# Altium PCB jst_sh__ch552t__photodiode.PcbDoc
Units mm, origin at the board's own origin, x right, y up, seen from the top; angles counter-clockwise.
Board outline 56 x 30 mm, 2 copper layers (Top, Bottom), stack 0 mm thick; 18 components, 10 nets, 67 pads, 25 vias.
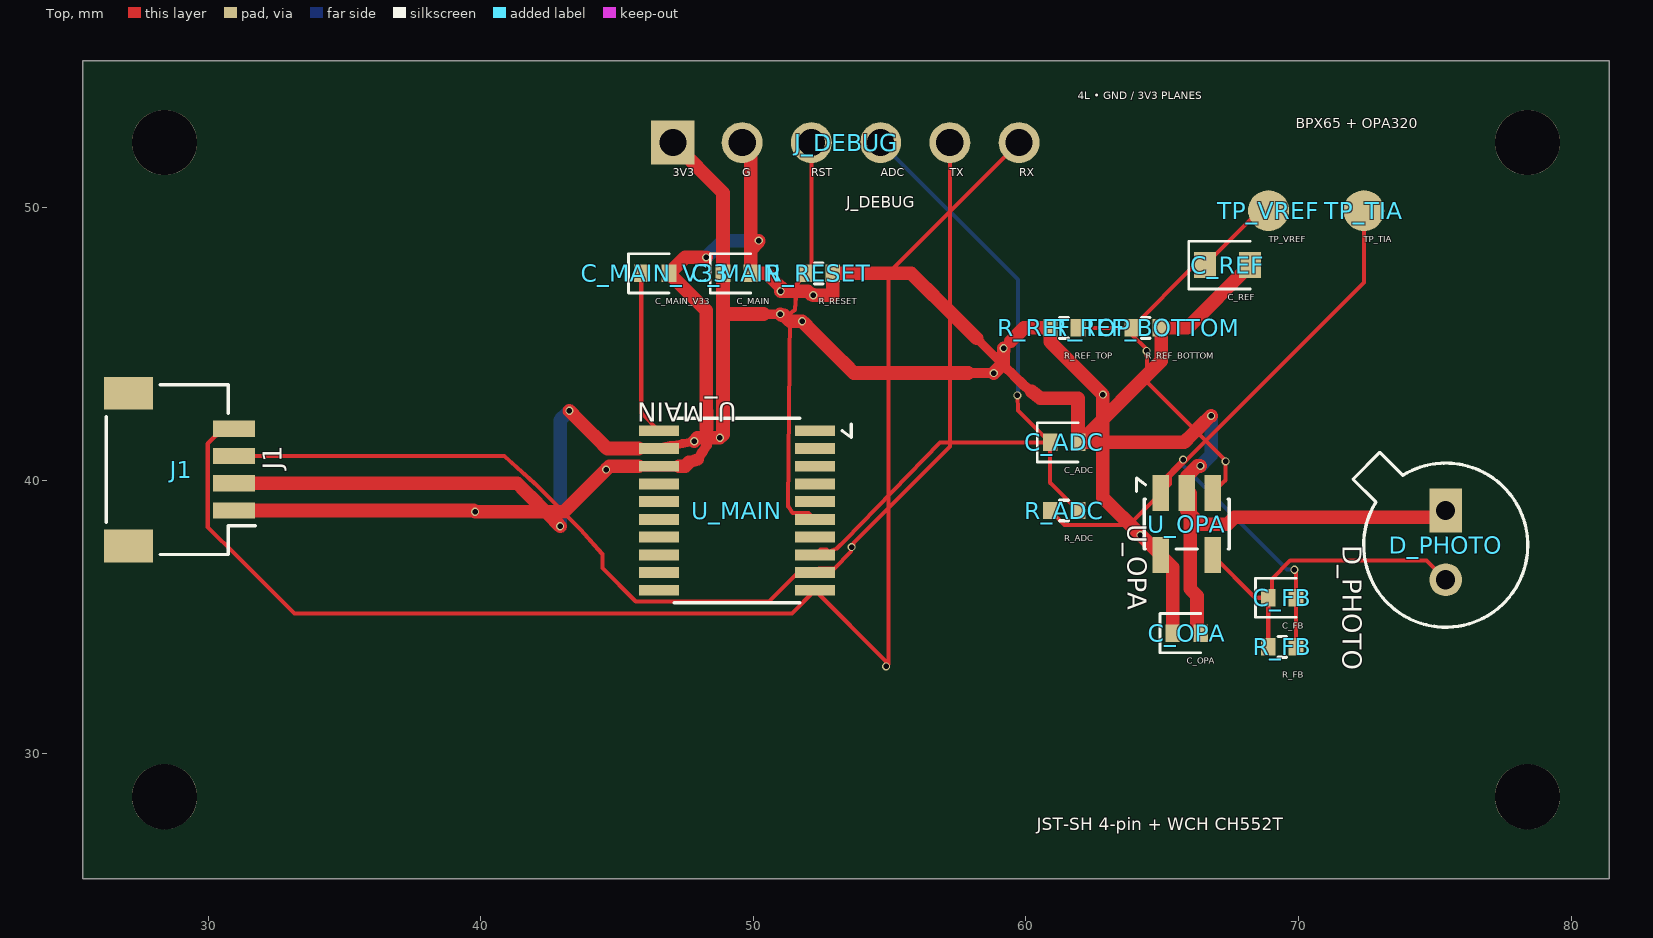
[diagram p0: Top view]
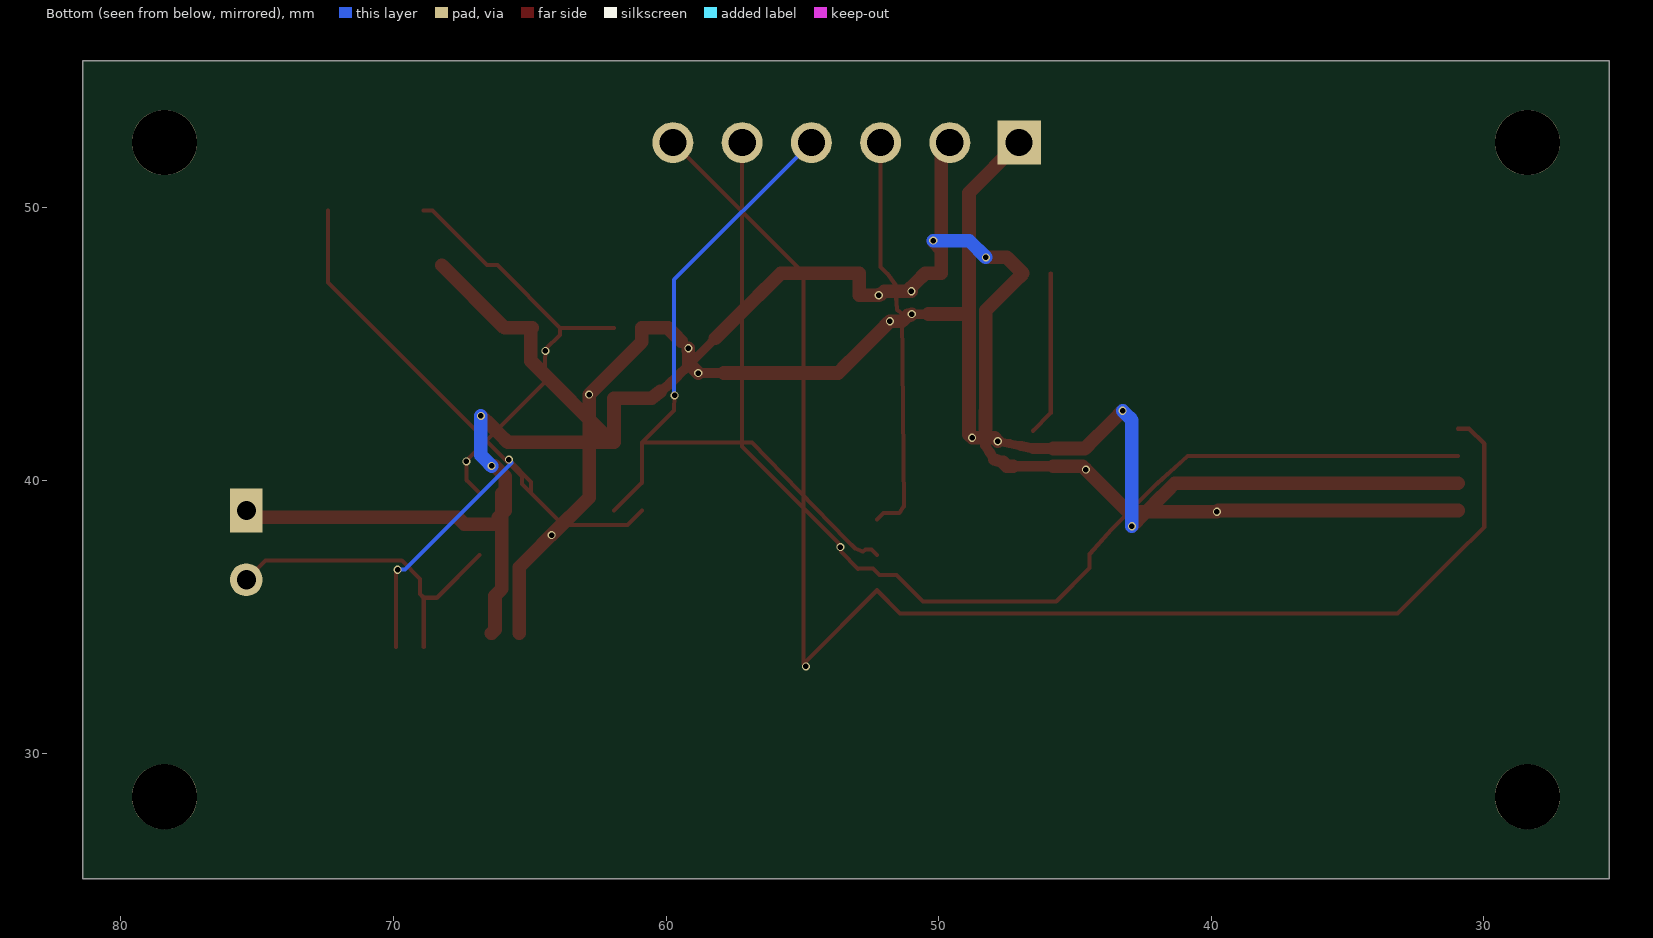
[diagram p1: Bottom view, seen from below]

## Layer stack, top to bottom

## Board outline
25.4,55.4 81.4,55.4 81.4,25.4 25.4,25.4

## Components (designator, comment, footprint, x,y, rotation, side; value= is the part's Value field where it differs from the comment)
C_ADC "" TSCIRCUIT-1.5600x0.6400mm 61.4,41.4 r0 top
C_FB "" TSCIRCUIT-1.5600x0.6400mm 69.4,35.7 r0 top
C_MAIN "" TSCIRCUIT-1.5600x0.6400mm 49.4,47.6 r0 top
C_MAIN_V33 "" TSCIRCUIT-1.5600x0.6400mm 46.4,47.6 r0 top
C_OPA "" TSCIRCUIT-1.5600x0.6400mm 65.9,34.4 r0 top
C_REF "" TSCIRCUIT-2.4500x0.9500mm 67.4,47.9 r0 top
D_PHOTO "" TSCIRCUIT-1.2000x3.9400mm 75.4,37.73 r270 top
J1 "" TSCIRCUIT-5.5500x6.8000mm 28.95,40.4 r90 top
J_DEBUG "" TSCIRCUIT-14.2000x1.5000mm 53.4,52.4 r0 top
R_ADC "" TSCIRCUIT-1.5600x0.6400mm 61.4,38.9 r0 top
R_FB "" TSCIRCUIT-1.5600x0.6400mm 69.4,33.9 r0 top
R_REF_BOTTOM "" TSCIRCUIT-1.5600x0.6400mm 64.4,45.6 r0 top
R_REF_TOP "" TSCIRCUIT-1.5600x0.6400mm 61.4,45.6 r0 top
R_RESET "" TSCIRCUIT-1.5600x0.6400mm 52.4,47.6 r0 top
TP_TIA "" TSCIRCUIT-1.5000x1.5000mm 72.4,49.9 r0 top
TP_VREF "" TSCIRCUIT-1.5000x1.5000mm 68.9,49.9 r0 top
U_MAIN "" TSCIRCUIT-7.2000x6.2500mm 49.4,38.9 r180 top
U_OPA "" TSCIRCUIT-2.5000x3.6000mm 65.9,38.4 r270 top

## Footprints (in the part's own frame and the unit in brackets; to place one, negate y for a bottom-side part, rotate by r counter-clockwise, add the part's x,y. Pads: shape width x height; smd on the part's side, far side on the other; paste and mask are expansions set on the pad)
TSCIRCUIT-1.2000x3.9400mm [mm]
  rect 1.6x1.2 hole 0.7: 1(-1.17,0)
  round 1.2 hole 0.7: 2(1.37,0)
  silkscreen extent -3.3,-3.4 3.11,3.01
TSCIRCUIT-1.5000x1.5000mm [mm]
  round 1.5 smd: 1(0,0)
TSCIRCUIT-1.5600x0.6400mm [mm]
  rect 0.54x0.64 smd: 1(-0.51,0) 2(0.51,0)
  silkscreen extent -0.98,-0.72 0.51,0.72
TSCIRCUIT-2.4500x0.9500mm [mm]
  rect 0.8x0.95 smd: 1(-0.825,0) 2(0.825,0)
  silkscreen extent -1.43,-0.87 0.82,0.87
TSCIRCUIT-2.5000x3.6000mm [mm]
  rect 1.325x0.6 smd: 1(-1.138,-0.95) 2(-1.138,0) 3(-1.138,0.95) 4(1.137,0.95) 5(1.137,-0.95)
  silkscreen extent -1.69,-1.84 0.91,1.56
TSCIRCUIT-5.5500x6.8000mm [mm]
  rect 1.2x1.8 smd: 1(-2.8,1.875) 1(2.8,1.875)
  rect 0.6x1.55 smd: 1(-1.5,-2) 2(-0.5,-2) 3(0.5,-2) 4(1.5,-2)
  silkscreen extent -3.11,-2.77 3.11,2.69
TSCIRCUIT-7.2000x6.2500mm [mm]
  rect 1.475x0.4 smd: 1(-2.862,-2.925) 2(-2.862,-2.275) 3(-2.862,-1.625) 4(-2.862,-0.975) 5(-2.862,-0.325) 6(-2.862,0.325) 7(-2.862,0.975) 8(-2.862,1.625) 9(-2.862,2.275) 10(-2.862,2.925) 11(2.863,2.925) 12(2.863,2.275) 13(2.863,1.625) 14(2.863,0.975) 15(2.863,0.325) 16(2.863,-0.325) 17(2.863,-0.975) 18(2.863,-1.625) 19(2.863,-2.275) 20(2.863,-2.925)
  silkscreen extent -4.19,-3.38 2.31,3.39
TSCIRCUIT-14.2000x1.5000mm [mm]
  rect 1.6x1.6 hole 1: 1(-6.35,0)
  round 1.5 hole 1: 2(-3.81,0) 3(-1.27,0) 4(1.27,0) 5(3.81,0) 6(6.35,0)

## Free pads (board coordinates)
  round 2.4 hole 2.4 unplated: NPTH-1(28.4,28.4) NPTH-2(78.4,52.4) NPTH-3(78.4,28.4) NPTH-4(28.4,52.4)

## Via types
v1: diameter 0.3, hole 0.2, Top to Bottom, 25 vias

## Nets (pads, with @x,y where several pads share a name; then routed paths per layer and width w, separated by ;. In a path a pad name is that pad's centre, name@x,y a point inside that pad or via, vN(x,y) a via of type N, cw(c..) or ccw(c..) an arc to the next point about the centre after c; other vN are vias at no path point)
ADC_IN: C_ADC.1 J_DEBUG.4 R_ADC.2 U_MAIN.8 | length 26.9
  Top w0.15: U_MAIN.8 52.463,37.476 52.678,37.476 52.791,37.392 53.072,37.516 53.357,37.795 56.841,41.4 C_ADC.1 ; v1(59.686,43.125) 59.715,42.575 C_ADC.1 ; R_ADC.2 60.89,39.92 C_ADC.1
  Bottom w0.15: J_DEBUG.4 59.703,47.367 59.703,43.235 59.703,43.166 v1(59.686,43.125)
GND: C_ADC.2 C_MAIN.2 C_MAIN_V33.2 C_OPA.2 C_REF.2 D_PHOTO.1 J1.1@30.95,38.9 J_DEBUG.2 R_REF_BOTTOM.2 R_RESET.2 U_MAIN.18 U_OPA.2 | length 86.7
  Top w0.325: 48.282,41.896 48.283,41.414 48.29,41.294 ; 58.193,45.213 58.536,44.872 58.878,44.531 59.221,44.191
  Top w0.35: 59.221,44.191 59.564,43.85
  Top w0.375: 47.962,40.775 48.126,41.034 48.29,41.294 ; 59.564,43.85 59.906,43.509 60.216,43.267
  Top w0.4: U_MAIN.18@45.8,40.525 U_MAIN.18 U_MAIN.18@47.275,40.525
  Top w0.45: 47.643,40.671 47.962,40.775
  Top w0.5: J1.1@30.95,38.9 39.749,38.9 v1(39.794,38.855) 40.26,38.855 40.726,38.855 41.192,38.855 41.657,38.855 42.123,38.855 42.589,38.855 43.055,38.855 43.363,39.163 43.671,39.471 43.979,39.779 44.287,40.087 44.595,40.395 v1(44.6,40.4) 44.725,40.525 U_MAIN.18@45.8,40.525 ; 47.275,40.525 47.496,40.525 47.643,40.671 ; v1(48.268,48.187) 47.497,48.187 C_MAIN_V33.2 47.25,47.26 47.591,46.919 47.931,46.579 48.271,46.239 48.273,45.756 48.274,45.274 48.275,44.791 48.276,44.309 48.277,43.826 48.278,43.344 48.28,42.861 48.281,42.379 48.282,41.896 ; J_DEBUG.2 49.91,52.08 C_MAIN.2 ; v1(50.2,48.8) 50.172,48.772 50.172,48.741 49.91,48.48 C_MAIN.2 ; 58.193,45.213 57.85,45.554 57.508,45.895 57.165,46.236 56.823,46.577 56.48,46.918 56.137,47.259 55.795,47.6 55.314,47.6 54.833,47.6 54.352,47.6 53.872,47.6 53.391,47.6 R_RESET.2 52.91,46.8 v1(52.2,46.8) 52.165,46.835 52.108,46.835 52,46.942 51.501,46.942 v1(51.001,46.942) 51.143,46.952 51.143,46.956 50.821,47.278 50.499,47.6 50.204,47.6 C_MAIN.2 ; 60.216,43.267 60.525,43.025 61.91,43.025 C_ADC.2 ; v1(66.402,40.535) 66.285,40.535 65.9,40.15 65.9,40.033 U_OPA.2 ; C_OPA.2 66.4,34.4 66.275,34.525 66.275,35.775 66.025,36.025 66.025,39.525 65.912,39.525 U_OPA.2 ; v1(66.795,42.369) 66.786,42.36 66.762,42.36 66.442,42.04 66.122,41.72 65.802,41.4 65.315,41.4 64.829,41.4 64.342,41.4 63.856,41.4 63.369,41.4 62.883,41.4 62.396,41.4 C_ADC.2 ; C_REF.2 65.925,45.6 R_REF_BOTTOM.2 64.961,45.549 64.961,44.385 61.976,41.4 C_ADC.2 ; D_PHOTO.1 75.152,38.652 74.654,38.652 74.155,38.652 73.656,38.652 73.158,38.652 72.902,38.652 72.9,38.65 67.65,38.65 67.4,38.4 66.15,38.4 66.15,38.65 65.9,38.9 U_OPA.2
  Bottom w0.5: v1(48.268,48.187) 48.881,48.8 v1(50.2,48.8) ; v1(66.402,40.535) 66.42,40.553 66.608,40.741 66.795,40.928 66.795,41.408 66.795,41.889 v1(66.795,42.369)
MAIN_RESET: J_DEBUG.3 R_RESET.1 U_MAIN.6 | length 14.9
  Top w0.15: J_DEBUG.3 52.13,47.84 R_RESET.1 51.592,47.191 51.522,46.267 51.343,46.118 51.277,39.049 51.446,38.805 51.74,38.805 51.729,38.81 52.027,38.81 U_MAIN.6
MAIN_V33: C_MAIN_V33.1 U_MAIN.20 | length 6
  Top w0.15: C_MAIN_V33.1 45.89,42.472 U_MAIN.20
PD_SUM: C_FB.1 D_PHOTO.2 R_FB.1 U_OPA.4 | length 12.2
  Top w0.15: U_OPA.4 68.412,35.7 C_FB.1 ; R_FB.1 C_FB.1 ; D_PHOTO.2 74.697,37.063 69.749,37.067 69.696,37.063 69.027,36.393 69.027,35.837 C_FB.1
TIA_OUT: C_FB.2 R_ADC.1 R_FB.2 TP_TIA.1 U_OPA.1 | length 28.6
  Top w0.15: R_ADC.1 61.42,38.37 63.782,38.37 U_OPA.1 ; v1(65.767,40.767) 64.95,39.95 U_OPA.1 ; v1(69.85,36.727) 69.881,36.7 69.881,36.688 69.91,36.659 C_FB.2 R_FB.2 ; TP_TIA.1 72.4,47.265 65.282,40.15 65.283,39.87 U_OPA.1
  Bottom w0.15: v1(65.767,40.767) 65.671,40.671 65.671,40.642 69.582,36.731 v1(69.85,36.727)
UART_MAIN_RX: J1.4 J_DEBUG.6 U_MAIN.10 | length 53.3
  Top w0.15: J1.4 30.55,41.9 29.985,41.35 29.984,38.3 31.1,37.2 33.171,35.129 51.364,35.129 51.417,35.129 U_MAIN.10 54.872,33.366 v1(54.872,33.181) 54.962,33.271 54.962,33.383 54.962,47.612 J_DEBUG.6
UART_MAIN_TX: J1.3 J_DEBUG.5 U_MAIN.9 | length 42.4
  Top w0.15: J1.3 40.863,40.9 41.972,39.902 43.664,38.202 44.46,37.303 44.46,36.788 45.687,35.562 50.582,35.562 51.553,36.532 52.17,36.532 U_MAIN.9 52.411,36.774 52.961,36.763 53.589,37.405 v1(53.603,37.56) 53.677,37.669 53.677,37.714 57.21,41.247 J_DEBUG.5
VCC_3V3: C_MAIN.1 C_OPA.1 J1.2 J_DEBUG.1 R_REF_TOP.1 U_MAIN.19 U_OPA.5 | length 63.3
  Top w0.325: U_MAIN.19@46.968,41.265 47.399,41.355 v1(47.83,41.444)
  Top w0.35: 50.383,46.107 50.687,46.107 v1(50.991,46.107) ; v1(59.182,44.85) v1@59.196,44.864
  Top w0.375: U_MAIN.19 U_MAIN.19@46.968,41.265 ; 57.884,43.944 58.351,43.944 v1(58.817,43.944) ; v1@59.196,44.864 59.441,45.109
  Top w0.4: U_MAIN.19@45.8,41.175 46.062,41.175 U_MAIN.19
  Top w0.45: v1(48.775,41.567) v1@48.872,41.664
  Top w0.5: J1.2 31.445,39.9 31.939,39.9 32.434,39.9 32.929,39.9 33.423,39.9 33.918,39.9 34.413,39.9 34.907,39.9 35.402,39.9 35.897,39.9 36.391,39.9 36.886,39.9 37.381,39.9 37.875,39.9 38.37,39.9 38.865,39.9 39.359,39.9 39.854,39.9 40.349,39.9 40.843,39.9 41.338,39.9 41.637,39.601 41.935,39.303 42.234,39.004 42.533,38.705 42.831,38.407 v1(42.912,38.326) ; v1(43.253,42.558) 43.599,42.212 43.944,41.866 44.29,41.521 44.636,41.175 45.111,41.175 45.587,41.175 U_MAIN.19@45.8,41.175 ; J_DEBUG.1 48.89,50.56 C_MAIN.1 ; v1(47.83,41.444) 47.953,41.567 v1(48.775,41.567) ; v1@48.872,41.664 48.89,41.682 C_MAIN.1 ; 50.383,46.107 48.89,46.107 C_MAIN.1 ; v1(50.991,46.107) 51.048,46.061 51.13,46.061 51.349,45.843 v1(51.787,45.843) 51.834,45.796 51.836,45.796 52.145,45.487 52.453,45.178 52.762,44.87 53.07,44.561 53.379,44.253 53.688,43.944 54.154,43.944 54.62,43.944 55.087,43.944 55.553,43.944 56.019,43.944 56.485,43.944 56.952,43.944 57.418,43.944 57.884,43.944 ; v1(58.817,43.944) 58.843,43.97 59.166,44.293 59.174,44.572 v1(59.182,44.85) ; 59.441,45.109 59.687,45.355 59.932,45.6 60.411,45.6 R_REF_TOP.1 60.89,45.086 v1(62.822,43.153) 62.822,39.378 v1(64.2,38) 64.213,38 U_OPA.5 65.39,36.822 C_OPA.1
  Bottom w0.5: v1(42.912,38.326) 42.912,38.812 42.912,39.299 42.912,39.785 42.912,40.271 42.912,40.758 42.912,41.244 42.912,41.73 42.912,42.217 43.165,42.47 v1(43.253,42.558)
VREF_0V5: C_REF.1 R_REF_BOTTOM.1 R_REF_TOP.2 TP_VREF.1 U_OPA.3 | length 16.4
  Top w0.15: R_REF_TOP.2 R_REF_BOTTOM.1 ; U_OPA.3 67.325,40.012 v1(67.325,40.701) 67.249,40.777 67.249,40.804 64.481,43.571 v1(64.43,44.753) 64.416,44.818 63.89,45.345 R_REF_BOTTOM.1 ; TP_VREF.1 68.575,49.9 C_REF.1 66.19,47.9 R_REF_BOTTOM.1
pads on no net: J1.1@27.075,37.6 J1.1@27.075,43.2 U_MAIN.1 U_MAIN.2 U_MAIN.3 U_MAIN.4 U_MAIN.5 U_MAIN.7 U_MAIN.11 U_MAIN.12 U_MAIN.13 U_MAIN.14 U_MAIN.15 U_MAIN.16 U_MAIN.17

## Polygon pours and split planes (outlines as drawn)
GND on Mid1 (solid): 81.1,55.1 25.7,55.1 25.7,25.7 81.1,25.7
VCC_3V3 on Mid2 (solid): 81.1,55.1 25.7,55.1 25.7,25.7 81.1,25.7

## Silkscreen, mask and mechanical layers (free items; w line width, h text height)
Top Overlay:
  text "4L • GND / 3V3 PLANES" at 61.9,53.9 h0.48
  text "BPX65 + OPA320" at 69.9,52.8 h0.65
  text "JST-SH 4-pin + WCH CH552T" at 60.4,27 h0.78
